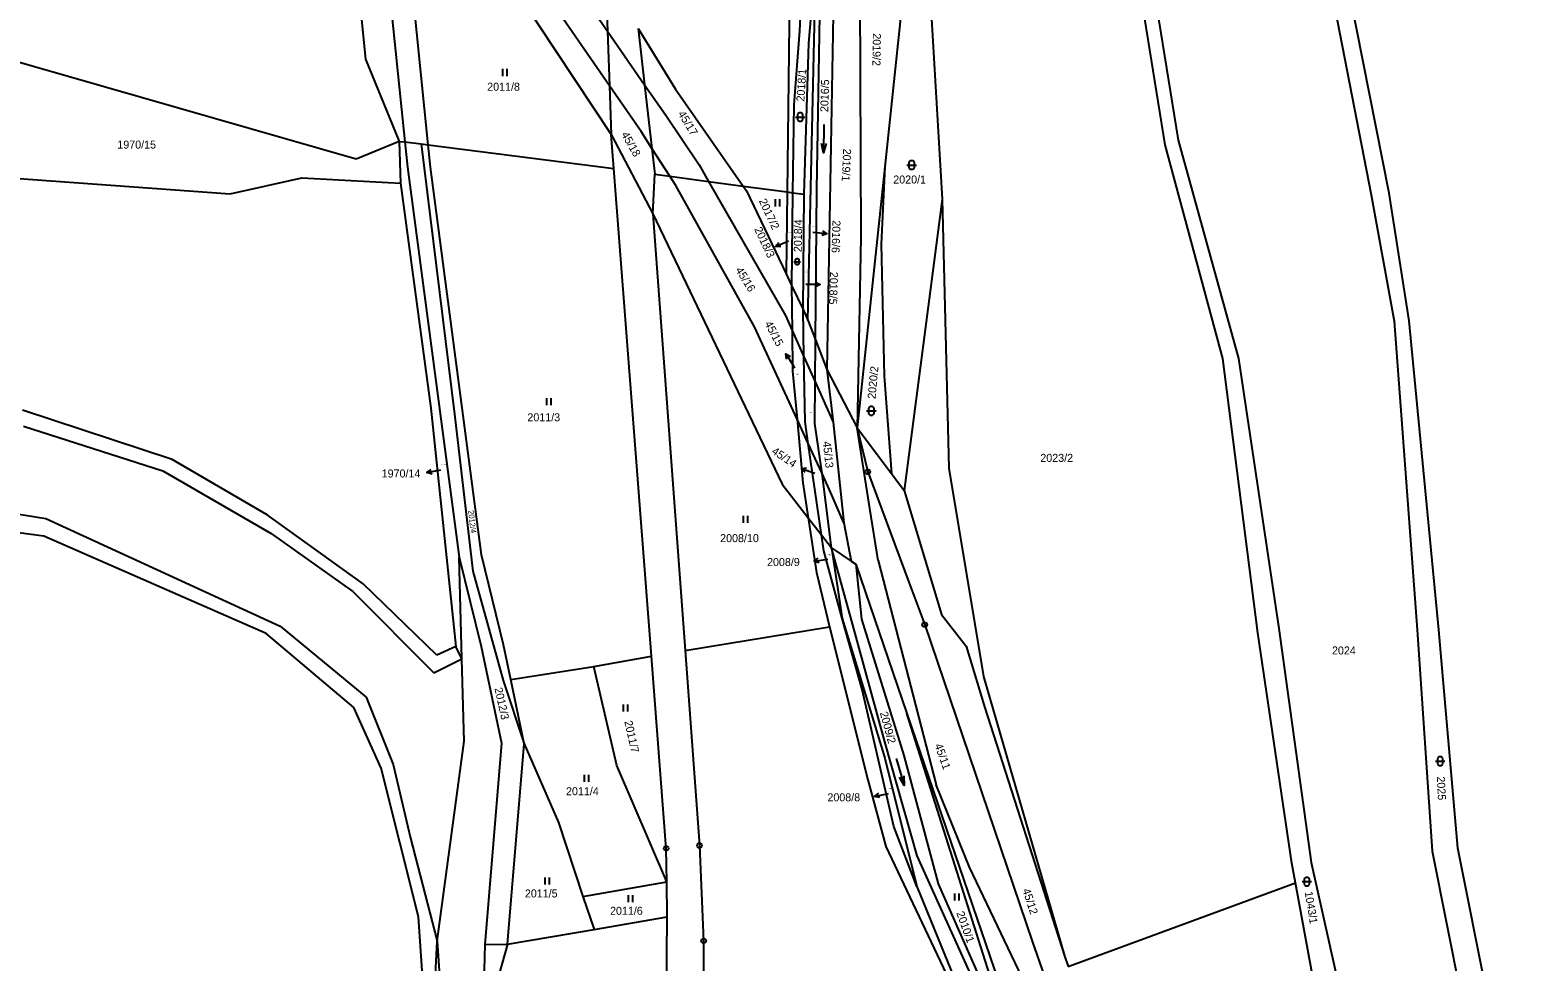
# Model space of a CAD drawing. Extents: x -609861 to -605046, y -1120287 to -1116307.
# Drawn here: x -607842.1 to -607526, y -1118395 to -1118197.1 of the extents above; entities that cross this region are included whole.
import ezdxf

# ---------------------------------------------------------------- set-up
doc = ezdxf.new("R2010")
doc.units = 0
for name, color, linetype in [('Vrstva 1', 7, 'Continuous'), ('Vrstva 2', 7, 'Continuous'), ('Vrstva 3', 7, 'Continuous'), ('Vrstva 4', 7, 'Continuous'), ('Vrstva 7', 7, 'Continuous'), ('Vrstva 8', 7, 'Continuous')]:
    doc.layers.add(name, color=color, linetype=linetype)

msp = doc.modelspace()

# ---------------------------------------------------------------- linework, layer by layer
at = {"layer": 'Vrstva 1'}
for p, q in [((-607765.2, -1118148.88), (-607718.51, -1118219.3)), ((-607600.79, -1118221.52), (-607612.32, -1118150.5)), ((-607609.46, -1118149.83), (-607598.03, -1118220.5)), ((-607775.63, -1118153.41), (-607770.74, -1118203.33)), ((-607680.49, -1118176.86), (-607681.15, -1118231.53)), ((-607766.44, -1118180.8), (-607762.35, -1118220.9)), ((-607757.38, -1118221.53), (-607761.49, -1118180.85)), ((-607677.57, -1118179.33), (-607678.5, -1118197.32)), ((-607676.69, -1118258.75), (-607674.99, -1118181.52)), ((-607676.54, -1118199.93), (-607674.99, -1118181.52)), ((-607719.75, -1118184.55), (-607719.29, -1118197.35)), ((-607674.79, -1118230.94), (-607673.96, -1118182.85)), ((-607665.71, -1118183.59), (-607665.44, -1118241.2)), ((-607566.26, -1118184.71), (-607557.04, -1118232.16)), ((-607553.24, -1118231.8), (-607562.56, -1118184.3)), ((-607671.23, -1118186.47), (-607672.68, -1118269.29)), ((-607656.24, -1118187.11), (-607660.39, -1118226.18)), ((-607650.77, -1118189.21), (-607648.16, -1118233.04)), ((-607719.29, -1118197.35), (-607718.88, -1118208.99)), ((-607712.76, -1118196.82), (-607711.4, -1118208.74)), ((-607712.76, -1118196.82), (-607704.84, -1118209.7)), ((-607678.5, -1118197.32), (-607679.71, -1118212.99)), ((-607772.67, -1118224.59), (-607863.89, -1118198.37)), ((-607677.53, -1118232.02), (-607676.54, -1118199.93)), ((-607770.74, -1118203.33), (-607763.56, -1118220.84)), ((-607718.88, -1118208.99), (-607718.51, -1118219.3)), ((-607711.4, -1118208.74), (-607709.84, -1118222.31)), ((-607704.84, -1118209.7), (-607690.46, -1118230.29)), ((-607679.71, -1118212.99), (-607679.95, -1118231.7)), ((-607717.95, -1118226.52), (-607718.51, -1118219.3)), ((-607718.51, -1118219.3), (-607709.64, -1118236.16)), ((-607763.56, -1118220.84), (-607772.67, -1118224.59)), ((-607763.56, -1118220.84), (-607762.35, -1118220.9)), ((-607763.56, -1118220.84), (-607763.26, -1118229.67)), ((-607762.35, -1118220.9), (-607758.91, -1118221.34)), ((-607762.35, -1118220.9), (-607761.8, -1118226.25)), ((-607758.91, -1118221.34), (-607751.78, -1118278.75)), ((-607758.91, -1118221.34), (-607757.38, -1118221.53)), ((-607757.38, -1118221.53), (-607717.95, -1118226.52)), ((-607756.9, -1118226.29), (-607757.38, -1118221.53)), ((-607709.84, -1118222.31), (-607709.22, -1118227.77)), ((-607588.55, -1118266.89), (-607600.79, -1118221.52)), ((-607598.03, -1118220.5), (-607585.25, -1118266.92)), ((-607761.8, -1118226.25), (-607750.79, -1118309.16)), ((-607746.08, -1118308.65), (-607756.9, -1118226.29)), ((-607709.96, -1118330.16), (-607717.95, -1118226.52)), ((-607660.39, -1118226.18), (-607666.27, -1118281.65)), ((-607660.39, -1118226.18), (-607661.11, -1118242.63)), ((-607860.03, -1118227.57), (-607799.5, -1118231.94)), ((-607799.5, -1118231.94), (-607784.26, -1118228.56)), ((-607784.26, -1118228.56), (-607763.26, -1118229.67)), ((-607763.26, -1118229.67), (-607756.84, -1118277.49)), ((-607709.64, -1118236.16), (-607709.22, -1118227.77)), ((-607709.22, -1118227.77), (-607706.05, -1118228.19)), ((-607706.05, -1118228.19), (-607697.81, -1118229.3)), ((-607697.81, -1118229.3), (-607690.46, -1118230.29)), ((-607690.46, -1118230.29), (-607681.15, -1118231.53)), ((-607690.46, -1118230.29), (-607689.74, -1118231.31)), ((-607689.74, -1118231.31), (-607681.36, -1118248.94)), ((-607681.15, -1118231.53), (-607681.36, -1118248.94)), ((-607681.15, -1118231.53), (-607679.95, -1118231.7)), ((-607679.95, -1118231.7), (-607680.18, -1118251.43)), ((-607679.95, -1118231.7), (-607677.53, -1118232.02)), ((-607677.74, -1118256.54), (-607677.53, -1118232.02)), ((-607675.09, -1118262.95), (-607674.79, -1118230.94)), ((-607557.04, -1118232.16), (-607552.11, -1118258.96)), ((-607548.96, -1118258.89), (-607553.24, -1118231.8)), ((-607648.16, -1118233.04), (-607656.29, -1118294.94)), ((-607709.64, -1118236.16), (-607702.8, -1118328.98)), ((-607709.64, -1118236.16), (-607682.19, -1118293.62)), ((-607665.44, -1118241.2), (-607666.27, -1118281.65)), ((-607661.11, -1118242.63), (-607660.54, -1118270.67)), ((-607681.36, -1118248.94), (-607680.18, -1118251.43)), ((-607680.18, -1118251.43), (-607680.06, -1118260.95)), ((-607680.18, -1118251.43), (-607677.74, -1118256.54)), ((-607677.55, -1118266.57), (-607677.74, -1118256.54)), ((-607677.74, -1118256.54), (-607676.69, -1118258.75)), ((-607680.06, -1118260.95), (-607679.95, -1118269.63)), ((-607676.69, -1118258.75), (-607675.09, -1118262.95)), ((-607552.11, -1118258.96), (-607547.23, -1118324.56)), ((-607542.63, -1118324.6), (-607548.96, -1118258.89)), ((-607675.18, -1118271.91), (-607675.09, -1118262.95)), ((-607675.09, -1118262.95), (-607672.68, -1118269.29)), ((-607677.29, -1118280.37), (-607677.55, -1118266.57)), ((-607581.14, -1118325.22), (-607588.55, -1118266.89)), ((-607585.25, -1118266.92), (-607576.68, -1118324.31)), ((-607679.95, -1118269.63), (-607679.01, -1118279.82)), ((-607672.68, -1118269.29), (-607671.36, -1118280.47)), ((-607672.68, -1118269.29), (-607666.27, -1118281.65)), ((-607660.54, -1118270.67), (-607658.98, -1118291.36)), ((-607675.26, -1118280.75), (-607675.18, -1118271.91)), ((-607811.81, -1118288.42), (-607843.58, -1118277.89)), ((-607756.84, -1118277.49), (-607751.55, -1118328.1)), ((-607751.78, -1118278.75), (-607747.92, -1118312.12)), ((-607679.01, -1118279.82), (-607677.77, -1118293.36)), ((-607843.36, -1118281.27), (-607813.74, -1118290.8)), ((-607676.62, -1118285.02), (-607677.29, -1118280.37)), ((-607673.7, -1118291.37), (-607675.26, -1118280.75)), ((-607671.36, -1118280.47), (-607669.05, -1118301.88)), ((-607663.52, -1118298.83), (-607666.27, -1118281.65)), ((-607666.27, -1118281.65), (-607658.98, -1118291.36)), ((-607673.85, -1118304.39), (-607676.62, -1118285.02)), ((-607791.63, -1118300.14), (-607811.81, -1118288.42)), ((-607813.74, -1118290.8), (-607790.77, -1118304.11)), ((-607671.71, -1118307.15), (-607673.7, -1118291.37)), ((-607658.98, -1118291.36), (-607656.29, -1118294.94)), ((-607682.19, -1118293.62), (-607676.64, -1118300.79)), ((-607677.77, -1118293.36), (-607676.64, -1118300.79)), ((-607656.29, -1118294.94), (-607648.3, -1118321.31)), ((-607851.95, -1118298.75), (-607838.64, -1118300.94)), ((-607661.75, -1118309.86), (-607663.52, -1118298.83)), ((-607838.64, -1118300.94), (-607788.84, -1118323.78)), ((-607771.24, -1118314.84), (-607791.63, -1118300.14)), ((-607676.64, -1118300.79), (-607674.87, -1118312.39)), ((-607676.64, -1118300.79), (-607673.85, -1118304.39)), ((-607669.05, -1118301.88), (-607667.5, -1118309.98)), ((-607839.07, -1118304.71), (-607852.16, -1118302.92)), ((-607791.85, -1118325.37), (-607839.07, -1118304.71)), ((-607790.77, -1118304.11), (-607773.39, -1118316.43)), ((-607673.36, -1118307.79), (-607673.85, -1118304.39)), ((-607673.85, -1118304.39), (-607671.71, -1118307.15)), ((-607741.38, -1118327.75), (-607746.08, -1118308.65)), ((-607669.41, -1118322.18), (-607673.36, -1118307.79)), ((-607667.47, -1118322.55), (-607671.71, -1118307.15)), ((-607671.71, -1118307.15), (-607669.41, -1118322.18)), ((-607671.71, -1118307.15), (-607667.5, -1118309.98)), ((-607750.23, -1118330.76), (-607750.79, -1118309.16)), ((-607750.79, -1118309.16), (-607746.13, -1118328.1)), ((-607667.5, -1118309.98), (-607666.5, -1118310.65)), ((-607666.5, -1118310.65), (-607665.31, -1118322.32)), ((-607666.5, -1118310.65), (-607655.66, -1118342.38)), ((-607661.75, -1118309.86), (-607649.49, -1118357.54)), ((-607755.57, -1118329.94), (-607771.24, -1118314.84)), ((-607747.92, -1118312.12), (-607741.48, -1118335.37)), ((-607674.87, -1118312.39), (-607672.15, -1118323.95)), ((-607773.39, -1118316.43), (-607756.22, -1118333.71)), ((-607648.3, -1118321.31), (-607643.1, -1118328.06)), ((-607788.84, -1118323.78), (-607770.6, -1118338.88)), ((-607702.8, -1118328.98), (-607672.15, -1118323.95)), ((-607672.15, -1118323.95), (-607663.99, -1118356.49)), ((-607665.2, -1118337.23), (-607669.41, -1118322.18)), ((-607669.41, -1118322.18), (-607660.36, -1118351.87)), ((-607660.39, -1118348.38), (-607667.47, -1118322.55)), ((-607665.31, -1118322.32), (-607656.31, -1118351.31)), ((-607651.9, -1118323.49), (-607629.03, -1118390.71)), ((-607576.68, -1118324.31), (-607569.78, -1118374.03)), ((-607547.23, -1118324.56), (-607544.1, -1118371.59)), ((-607773.17, -1118341.07), (-607791.85, -1118325.37)), ((-607573.88, -1118374.19), (-607581.14, -1118325.22)), ((-607538.6, -1118370.99), (-607542.63, -1118324.6)), ((-607756.22, -1118333.71), (-607750.23, -1118330.76)), ((-607751.55, -1118328.1), (-607755.57, -1118329.94)), ((-607750.23, -1118330.76), (-607751.55, -1118328.1)), ((-607749.78, -1118348.27), (-607750.23, -1118330.76)), ((-607746.13, -1118328.1), (-607741.79, -1118348.65)), ((-607739.84, -1118335.12), (-607741.38, -1118327.75)), ((-607722.16, -1118332.39), (-607709.96, -1118330.16)), ((-607706.81, -1118371.05), (-607709.96, -1118330.16)), ((-607702.8, -1118328.98), (-607699.75, -1118370.42)), ((-607643.1, -1118328.06), (-607639.1, -1118341.19)), ((-607739.84, -1118335.12), (-607722.16, -1118332.39)), ((-607717.34, -1118353.39), (-607722.16, -1118332.39)), ((-607741.48, -1118335.37), (-607736.99, -1118348.8)), ((-607736.99, -1118348.8), (-607739.84, -1118335.12)), ((-607770.6, -1118338.88), (-607764.8, -1118353.18)), ((-607658.43, -1118366.34), (-607665.2, -1118337.23)), ((-607767.38, -1118353.98), (-607773.17, -1118341.07)), ((-607626.28, -1118434.95), (-607655.66, -1118342.38)), ((-607655.66, -1118342.38), (-607633.97, -1118405.89)), ((-607639.1, -1118341.19), (-607622.19, -1118393.87)), ((-607755.46, -1118390.76), (-607749.78, -1118348.27)), ((-607741.79, -1118348.65), (-607745.32, -1118391.46)), ((-607740.57, -1118391.41), (-607736.99, -1118348.8)), ((-607736.99, -1118348.8), (-607729.67, -1118365.56)), ((-607653.52, -1118372.62), (-607660.39, -1118348.38)), ((-607660.36, -1118351.87), (-607653.54, -1118379.09)), ((-607656.31, -1118351.31), (-607649.03, -1118378.53)), ((-607759.44, -1118385.57), (-607767.38, -1118353.98)), ((-607764.8, -1118353.18), (-607761.15, -1118368.88)), ((-607706.71, -1118378.16), (-607717.34, -1118353.39)), ((-607663.99, -1118356.49), (-607660.12, -1118370.59)), ((-607642.4, -1118375), (-607649.49, -1118357.54)), ((-607729.67, -1118365.56), (-607724.52, -1118381.26)), ((-607653.54, -1118379.09), (-607658.43, -1118366.34)), ((-607761.15, -1118368.88), (-607755.46, -1118390.76)), ((-607706.71, -1118378.16), (-607706.81, -1118371.05)), ((-607699.75, -1118370.42), (-607698.86, -1118390.68)), ((-607660.12, -1118370.59), (-607647.3, -1118397.68)), ((-607544.1, -1118371.59), (-607531.82, -1118432.76)), ((-607525.99, -1118434.27), (-607538.6, -1118370.99)), ((-607641.07, -1118400.03), (-607653.52, -1118372.62)), ((-607630.48, -1118399.97), (-607642.4, -1118375)), ((-607573.11, -1118378.35), (-607573.88, -1118374.19)), ((-607569.78, -1118374.03), (-607556.29, -1118434.42)), ((-607724.52, -1118381.26), (-607706.71, -1118378.16)), ((-607706.61, -1118385.6), (-607706.71, -1118378.16)), ((-607724.52, -1118381.26), (-607722.12, -1118388.25)), ((-607653.54, -1118379.09), (-607641.29, -1118409.31)), ((-607649.03, -1118378.53), (-607639.21, -1118400.88)), ((-607621.4, -1118396.15), (-607573.11, -1118378.35)), ((-607562.64, -1118434.7), (-607573.11, -1118378.35)), ((-607757.07, -1118420.64), (-607759.44, -1118385.57)), ((-607722.12, -1118388.25), (-607706.61, -1118385.6)), ((-607707.41, -1118469.4), (-607706.61, -1118385.6)), ((-607757.07, -1118420.64), (-607755.46, -1118390.76)), ((-607755.46, -1118390.76), (-607753.43, -1118421.92)), ((-607740.57, -1118391.41), (-607722.12, -1118388.25)), ((-607698.86, -1118390.68), (-607699.1, -1118444.38)), ((-607629.03, -1118390.71), (-607626.47, -1118398.24)), ((-607745.32, -1118391.46), (-607740.57, -1118391.41)), ((-607740.57, -1118391.41), (-607743.99, -1118403.74)), ((-607622.19, -1118393.87), (-607621.4, -1118396.15))]:
    msp.add_line(p, q, dxfattribs=at)
msp.add_lwpolyline([(-607666.27, -1118281.65), (-607663.97, -1118291.01), (-607655.26, -1118314.46), (-607651.9, -1118323.49)], dxfattribs=at)
at = {"layer": 'Vrstva 3'}
for p, q in [((-607741.6, -1118205.4), (-607741.6, -1118206.9)), ((-607740.6, -1118206.9), (-607740.6, -1118205.4)), ((-607673.29, -1118217.21), (-607673.37, -1118223.21)), ((-607683.7, -1118233.1), (-607683.7, -1118234.6)), ((-607682.7, -1118234.6), (-607682.7, -1118233.1)), ((-607732.24, -1118275.37), (-607732.24, -1118276.87)), ((-607731.24, -1118276.87), (-607731.24, -1118275.37)), ((-607690.47, -1118300.37), (-607690.47, -1118301.87)), ((-607689.47, -1118301.87), (-607689.47, -1118300.37)), ((-607715.95, -1118340.42), (-607715.95, -1118341.92)), ((-607714.95, -1118341.92), (-607714.95, -1118340.42)), ((-607657.922, -1118351.891), (-607656.238, -1118357.649)), ((-607724.24, -1118355.4), (-607724.24, -1118356.9)), ((-607723.24, -1118356.9), (-607723.24, -1118355.4)), ((-607732.64, -1118377.18), (-607732.64, -1118378.68)), ((-607731.64, -1118378.68), (-607731.64, -1118377.18)), ((-607714.89, -1118380.94), (-607714.89, -1118382.44)), ((-607713.89, -1118382.44), (-607713.89, -1118380.94)), ((-607645.56, -1118380.61), (-607645.56, -1118382.11)), ((-607644.56, -1118382.11), (-607644.56, -1118380.61))]:
    msp.add_line(p, q, dxfattribs=at)
for points in [[(-607679.38, -1118215.61), (-607678.11, -1118215.61), (-607677.38, -1118215.61)], [(-607672.843, -1118221.217), (-607673.37, -1118223.21), (-607673.843, -1118221.203)], [(-607655.66, -1118225.81), (-607654.39, -1118225.81), (-607653.66, -1118225.81)], [(-607679.71, -1118246.35), (-607678.821, -1118246.35), (-607678.31, -1118246.35)], [(-607664.24, -1118278.05), (-607662.97, -1118278.05), (-607662.24, -1118278.05)], [(-607543.38, -1118352.48), (-607542.11, -1118352.48), (-607541.38, -1118352.48)], [(-607656.319, -1118355.589), (-607656.238, -1118357.649), (-607657.279, -1118355.87)], [(-607571.69, -1118378.08), (-607570.42, -1118378.08), (-607569.69, -1118378.08)]]:
    msp.add_lwpolyline(points, dxfattribs=at)
for points in [[(-607678.88, -1118215.11), (-607678.78, -1118214.82), (-607678.53, -1118214.64), (-607678.22, -1118214.64), (-607677.97, -1118214.82), (-607677.87, -1118215.11), (-607677.87, -1118216.11), (-607677.97, -1118216.4), (-607678.22, -1118216.58), (-607678.53, -1118216.58), (-607678.78, -1118216.4), (-607678.88, -1118216.11)], [(-607655.16, -1118225.31), (-607655.06, -1118225.02), (-607654.81, -1118224.84), (-607654.5, -1118224.84), (-607654.25, -1118225.02), (-607654.15, -1118225.31), (-607654.15, -1118226.31), (-607654.25, -1118226.6), (-607654.5, -1118226.78), (-607654.81, -1118226.78), (-607655.06, -1118226.6), (-607655.16, -1118226.31)], [(-607679.36, -1118246), (-607679.29, -1118245.797), (-607679.115, -1118245.671), (-607678.898, -1118245.671), (-607678.723, -1118245.797), (-607678.653, -1118246), (-607678.653, -1118246.7), (-607678.723, -1118246.903), (-607678.898, -1118247.029), (-607679.115, -1118247.029), (-607679.29, -1118246.903), (-607679.36, -1118246.7)], [(-607663.74, -1118277.55), (-607663.64, -1118277.26), (-607663.39, -1118277.08), (-607663.08, -1118277.08), (-607662.83, -1118277.26), (-607662.73, -1118277.55), (-607662.73, -1118278.55), (-607662.83, -1118278.84), (-607663.08, -1118279.02), (-607663.39, -1118279.02), (-607663.64, -1118278.84), (-607663.74, -1118278.55)], [(-607542.88, -1118351.98), (-607542.78, -1118351.69), (-607542.53, -1118351.51), (-607542.22, -1118351.51), (-607541.97, -1118351.69), (-607541.87, -1118351.98), (-607541.87, -1118352.98), (-607541.97, -1118353.27), (-607542.22, -1118353.45), (-607542.53, -1118353.45), (-607542.78, -1118353.27), (-607542.88, -1118352.98)], [(-607571.19, -1118377.58), (-607571.09, -1118377.29), (-607570.84, -1118377.11), (-607570.53, -1118377.11), (-607570.28, -1118377.29), (-607570.18, -1118377.58), (-607570.18, -1118378.58), (-607570.28, -1118378.87), (-607570.53, -1118379.05), (-607570.84, -1118379.05), (-607571.09, -1118378.87), (-607571.19, -1118378.58)]]:
    msp.add_lwpolyline(points, close=True, dxfattribs=at)
at = {"layer": 'Vrstva 4'}
for p, q in [((-607760.31, -1118138.21), (-607719.29, -1118197.35)), ((-607718.88, -1118208.99), (-607765.39, -1118141.66)), ((-607719.29, -1118197.35), (-607711.4, -1118208.74)), ((-607712.17, -1118218.7), (-607718.88, -1118208.99)), ((-607711.4, -1118208.74), (-607706.88, -1118215.25)), ((-607706.88, -1118215.25), (-607699.84, -1118225.77)), ((-607709.84, -1118222.31), (-607712.17, -1118218.7)), ((-607706.05, -1118228.19), (-607709.84, -1118222.31)), ((-607699.84, -1118225.77), (-607697.81, -1118229.3)), ((-607704.78, -1118230.17), (-607706.05, -1118228.19)), ((-607697.81, -1118229.3), (-607681.46, -1118257.8)), ((-607688.04, -1118260.19), (-607704.78, -1118230.17)), ((-607648.16, -1118233.04), (-607646.79, -1118290.2)), ((-607681.46, -1118257.8), (-607680.06, -1118260.95)), ((-607679.01, -1118279.82), (-607688.04, -1118260.19)), ((-607680.06, -1118260.95), (-607677.55, -1118266.57)), ((-607677.55, -1118266.57), (-607675.18, -1118271.91)), ((-607675.18, -1118271.91), (-607671.36, -1118280.47)), ((-607676.62, -1118285.02), (-607679.01, -1118279.82)), ((-607673.7, -1118291.37), (-607676.62, -1118285.02)), ((-607671.6, -1118295.95), (-607673.7, -1118291.37)), ((-607646.79, -1118290.2), (-607639.39, -1118334.53)), ((-607669.05, -1118301.88), (-607671.6, -1118295.95)), ((-607639.39, -1118334.53), (-607622.19, -1118393.87)), ((-607745.32, -1118391.46), (-607745.7, -1118404.76))]:
    msp.add_line(p, q, dxfattribs=at)
at = {"layer": 'Vrstva 7'}
for p, q in [((-607683.573, -1118243.149), (-607680.85, -1118241.89)), ((-607672.694, -1118240.412), (-607675.68, -1118240.12)), ((-607674.13, -1118251.221), (-607677.13, -1118251.22)), ((-607681.366, -1118265.937), (-607679.79, -1118268.49)), ((-607679.48, -1118269), (-607679.79, -1118268.49)), ((-607757.656, -1118291.177), (-607754.71, -1118290.61)), ((-607678.089, -1118290.33), (-607675.24, -1118291.27)), ((-607675.412, -1118310.026), (-607672.45, -1118309.55)), ((-607662.541, -1118359.968), (-607659.61, -1118359.33))]:
    msp.add_line(p, q, dxfattribs=at)
for points in [[(-607682.455, -1118243.183), (-607683.573, -1118243.149), (-607682.875, -1118242.276)], [(-607673.641, -1118239.817), (-607672.694, -1118240.412), (-607673.738, -1118240.812)], [(-607675.13, -1118250.721), (-607674.13, -1118251.221), (-607675.13, -1118251.721)], [(-607681.266, -1118267.051), (-607681.366, -1118265.937), (-607680.415, -1118266.525)], [(-607756.579, -1118291.479), (-607757.656, -1118291.177), (-607756.768, -1118290.497)], [(-607677.296, -1118291.118), (-607678.089, -1118290.33), (-607676.983, -1118290.168)], [(-607674.345, -1118310.361), (-607675.412, -1118310.026), (-607674.504, -1118309.373)], [(-607661.458, -1118360.244), (-607662.541, -1118359.968), (-607661.671, -1118359.267)]]:
    msp.add_lwpolyline(points, dxfattribs=at)
at = {"layer": 'Vrstva 8'}
for p, q in [((-607664.09, -1118291.01), (-607663.85, -1118291.01)), ((-607652.02, -1118323.49), (-607651.78, -1118323.49)), ((-607706.93, -1118371.05), (-607706.69, -1118371.05)), ((-607699.87, -1118370.42), (-607699.63, -1118370.42)), ((-607698.98, -1118390.68), (-607698.74, -1118390.68))]:
    msp.add_line(p, q, dxfattribs=at)
for points in [[(-607663.82, -1118290.53), (-607663.57, -1118290.71), (-607663.47, -1118291), (-607663.57, -1118291.29), (-607663.82, -1118291.47), (-607664.13, -1118291.47), (-607664.38, -1118291.29), (-607664.48, -1118291), (-607664.38, -1118290.71), (-607664.13, -1118290.53)], [(-607651.75, -1118323.01), (-607651.5, -1118323.19), (-607651.4, -1118323.48), (-607651.5, -1118323.77), (-607651.75, -1118323.95), (-607652.06, -1118323.95), (-607652.31, -1118323.77), (-607652.41, -1118323.48), (-607652.31, -1118323.19), (-607652.06, -1118323.01)], [(-607706.66, -1118370.57), (-607706.41, -1118370.75), (-607706.31, -1118371.04), (-607706.41, -1118371.33), (-607706.66, -1118371.51), (-607706.97, -1118371.51), (-607707.22, -1118371.33), (-607707.32, -1118371.04), (-607707.22, -1118370.75), (-607706.97, -1118370.57)], [(-607699.6, -1118369.94), (-607699.35, -1118370.12), (-607699.25, -1118370.41), (-607699.35, -1118370.7), (-607699.6, -1118370.88), (-607699.91, -1118370.88), (-607700.16, -1118370.7), (-607700.26, -1118370.41), (-607700.16, -1118370.12), (-607699.91, -1118369.94)], [(-607698.71, -1118390.2), (-607698.46, -1118390.38), (-607698.36, -1118390.67), (-607698.46, -1118390.96), (-607698.71, -1118391.14), (-607699.02, -1118391.14), (-607699.27, -1118390.96), (-607699.37, -1118390.67), (-607699.27, -1118390.38), (-607699.02, -1118390.2)]]:
    msp.add_lwpolyline(points, close=True, dxfattribs=at)

# ---------------------------------------------------------------- texts
at = {"layer": 'Vrstva 2'}
for s, height, rotation, p in [('2019/2', 1.7, 269.11828, (-607662.894, -1118197.807)), ('2018/1', 1.7, 86.40204, (-607677.475, -1118212.363)), ('2016/5', 1.7, 88.17821, (-607672.402, -1118214.583)), ('45/17', 1.7, 301.49039, (-607704.406, -1118214.932)), ('45/18', 1.7, 299.71422, (-607716.432, -1118219.316)), ('2019/1', 1.7, 267.28481, (-607669.201, -1118222.297)), ('2017/2', 1.7, 295.18786, (-607687.179, -1118233.425)), ('2018/4', 1.7, 89.09494, (-607678.026, -1118244.323)), ('45/16', 1.7, 301.49039, (-607692.166, -1118248.112)), ('2020/2', 1.7, 84.62587, (-607662.358, -1118275.564)), ('45/13', 1.7, 276.28025, (-607673.554, -1118284.626)), ('2012/4', 1.2, 276.28025, (-607748.892, -1118299.227)), ('2012/3', 1.7, 282.58278, (-607743.328, -1118337.032)), ('2009/2', 1.7, 285.27569, (-607661.437, -1118342.219)), ('2011/7', 1.7, 282.58278, (-607715.718, -1118344.072)), ('45/11', 1.7, 289.80205, (-607649.83, -1118349.083)), ('2025', 1.7, 272.72791, (-607543.069, -1118355.777)), ('45/12', 1.7, 288.02588, (-607631.157, -1118379.846)), ('1043/1', 1.7, 279.31693, (-607571.163, -1118380.307)), ('2010/1', 1.7, 289.80205, (-607645.2, -1118384.743))]:
    msp.add_text(s, height=height, rotation=rotation, dxfattribs=at).set_placement(p)
for s, height, p in [('2011/8', 1.7, (-607744.853, -1118210.02)), ('1970/15', 1.7, (-607823.437, -1118222.32)), ('2020/1', 1.7, (-607658.573, -1118229.74)), ('2016/6', 0.2, (-607675.902, -1118238.94)), ('2018/3', 0.2, (-607680.912, -1118240.28)), ('2018/5', 0.2, (-607677.202, -1118248.7)), ('45/15', 0.2, (-607679.172, -1118270.36)), ('2011/3', 1.7, (-607736.313, -1118280.27)), ('45/14', 0.2, (-607676.592, -1118278.51)), ('1970/14', 0.2, (-607754.584, -1118289.58)), ('2023/2', 1.7, (-607627.323, -1118288.89)), ('2008/10', 1.7, (-607695.353, -1118305.95)), ('2008/9', 0.2, (-607672.622, -1118308.76)), ('2024', 1.7, (-607565.353, -1118329.82)), ('2011/4', 1.7, (-607728.103, -1118359.73)), ('2008/8', 0.2, (-607659.672, -1118358.42)), ('2011/5', 1.7, (-607736.843, -1118381.45)), ('2011/6', 1.7, (-607718.753, -1118385.14))]:
    msp.add_text(s, height=height, dxfattribs=at).set_placement(p)
at = {"layer": 'Vrstva 7'}
for s, rotation, p in [('2018/3', 295.18786, (-607688.155, -1118239.429)), ('2016/6', 268.20154, (-607671.467, -1118237.521)), ('2018/5', 268.20154, (-607671.997, -1118248.481)), ('45/15', 297.88076, (-607685.964, -1118259.49)), ('45/14', 325.7838, (-607684.565, -1118287.007))]:
    msp.add_text(s, height=1.7, rotation=rotation, dxfattribs=at).set_placement(p)
for s, p in [('1970/14', (-607767.272, -1118292.21)), ('2008/9', (-607685.391, -1118311.03)), ('2008/8', (-607672.561, -1118361.03))]:
    msp.add_text(s, height=1.7, dxfattribs=at).set_placement(p)

doc.saveas('drawing.dxf')
